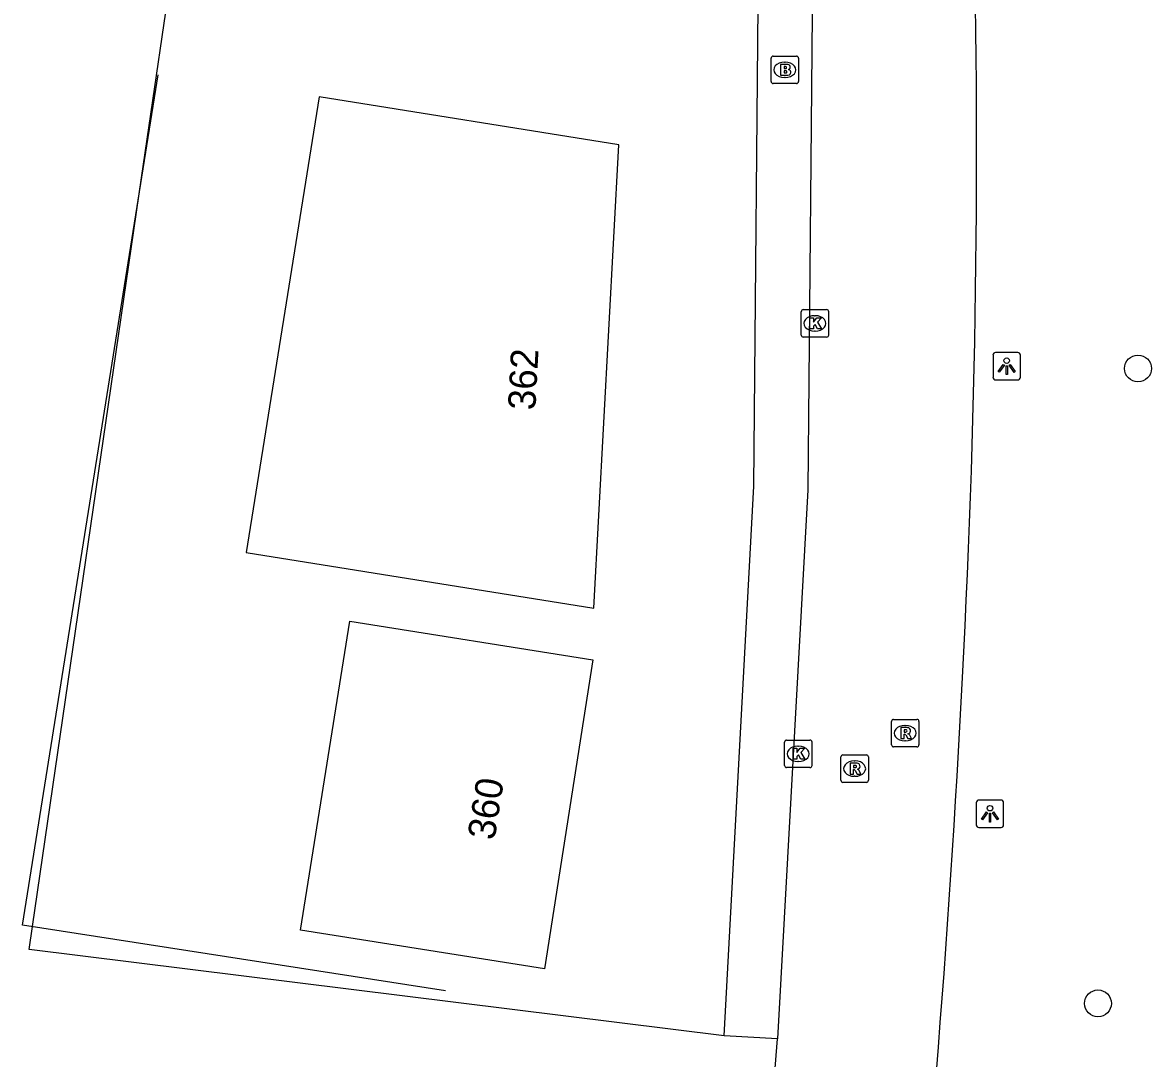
# Model space of a CAD drawing. Extents: x 154324 to 155743, y 382939 to 384183.
# Drawn here: x 155354.48 to 155395.6, y 383333.57 to 383371.29 of the extents above; entities that cross this region are included whole.
import ezdxf

# ---------------------------------------------------------------- set-up
doc = ezdxf.new("R2010")
doc.units = 0
for name, color, linetype in [('IMGEO_Boom', 7, 'Continuous'), ('IMGEO_Brandkraan', 7, 'Continuous'), ('IMGEO_Groenvoorziening', 7, 'Continuous'), ('IMGEO_Hek', 7, 'Continuous'), ('IMGEO_Kolk', 7, 'Continuous'), ('IMGEO_Lichtpunt', 7, 'Continuous'), ('IMGEO_Pand', 7, 'Continuous'), ('IMGEO_Pand_nummerreeks', 7, 'Continuous'), ('IMGEO_Rijbaan_lokaal_open', 7, 'Continuous'), ('IMGEO_Rioolput', 7, 'Continuous'), ('IMGEO_Voetpad_open', 7, 'Continuous')]:
    doc.layers.add(name, color=color, linetype=linetype)

msp = doc.modelspace()

# ---------------------------------------------------------------- linework, layer by layer
at = {"layer": 'IMGEO_Boom'}
for centre in [(155395.106, 383358.693), (155393.648, 383335.575)]:
    msp.add_circle(centre, 0.489, dxfattribs=at)
at = {"layer": 'IMGEO_Brandkraan'}
for p, q in [((155381.816, 383370.068), (155382.668, 383370.068)), ((155381.741, 383369.142), (155381.741, 383369.994)), ((155382.229, 383369.848), (155382.254, 383369.848)), ((155382.742, 383369.994), (155382.742, 383369.142)), ((155382.252, 383369.288), (155382.227, 383369.288)), ((155382.668, 383369.068), (155381.816, 383369.068))]:
    msp.add_line(p, q, dxfattribs=at)
for points in [[(155381.816, 383370.068), (155382.668, 383370.068)], [(155381.741, 383369.142), (155381.741, 383369.994)], [(155382.089, 383369.768), (155382.089, 383369.368), (155382.302, 383369.368)], [(155382.32, 383369.768), (155382.089, 383369.768)], [(155382.268, 383369.687), (155382.214, 383369.687), (155382.214, 383369.611)], [(155382.742, 383369.994), (155382.742, 383369.142)], [(155382.214, 383369.611), (155382.267, 383369.611)], [(155382.276, 383369.535), (155382.214, 383369.535), (155382.214, 383369.454)], [(155382.214, 383369.454), (155382.276, 383369.454)], [(155382.668, 383369.068), (155381.816, 383369.068)]]:
    msp.add_lwpolyline(points, dxfattribs=at)
for centre, radius, start, end in [((155381.818, 383369.992), 0.0765, 91.552, 178.448), ((155381.818, 383369.992), 0.0765, 91.552, 178.448), ((155382.666, 383369.992), 0.0765, 1.552, 88.448), ((155382.666, 383369.992), 0.0765, 1.552, 88.448), ((155382.269, 383369.649), 0.0379, 267.8285, 90.9355), ((155382.324, 383369.623), 0.145, 59.4692, 91.5367), ((155382.349, 383369.67), 0.0922, 285.5137, 58.1501), ((155382.277, 383369.494), 0.0404, 269.8759, 90.5077), ((155382.308, 383369.619), 0.251, 268.6676, 293.5347), ((155382.354, 383369.478), 0.105, 301.3115, 78.989), ((155381.818, 383369.144), 0.0765, 181.552, 268.448), ((155381.818, 383369.144), 0.0765, 181.552, 268.448), ((155382.666, 383369.144), 0.0765, 271.552, 358.448), ((155382.666, 383369.144), 0.0765, 271.552, 358.448)]:
    msp.add_arc(centre, radius, start, end, dxfattribs=at)
for centre, major_axis, ratio, start_param, end_param in [((155382.228, 383369.568), (-0.387, 0.002), 0.722429, 4.712389, 7.853982), ((155382.253, 383369.568), (-0.39, 0.002), 0.717154, 1.570796, 4.712389)]:
    msp.add_ellipse(centre, major_axis=major_axis, ratio=ratio, start_param=start_param, end_param=end_param, dxfattribs=at)
at = {"layer": 'IMGEO_Groenvoorziening'}
msp.add_lwpolyline([(155380.034, 383334.398), (155354.723, 383337.539), (155354.844, 383338.369), (155358.814, 383365.632), (155360.106, 383374.508)], dxfattribs=at)
at = {"layer": 'IMGEO_Hek'}
msp.add_lwpolyline([(155369.884, 383336.037), (155354.478, 383338.426), (155359.411, 383369.381)], dxfattribs=at)
at = {"layer": 'IMGEO_Kolk'}
for p, q in [((155382.838, 383359.91), (155382.838, 383360.762)), ((155382.913, 383360.836), (155383.765, 383360.836)), ((155383.326, 383360.616), (155383.351, 383360.616)), ((155383.839, 383360.762), (155383.839, 383359.91)), ((155383.765, 383359.836), (155382.913, 383359.836)), ((155383.349, 383360.056), (155383.324, 383360.056)), ((155382.231, 383344.237), (155382.231, 383345.089)), ((155382.306, 383345.163), (155383.158, 383345.163)), ((155383.232, 383345.089), (155383.232, 383344.237)), ((155382.719, 383344.943), (155382.744, 383344.943)), ((155383.158, 383344.163), (155382.306, 383344.163)), ((155382.742, 383344.383), (155382.717, 383344.383))]:
    msp.add_line(p, q, dxfattribs=at)
for points in [[(155382.838, 383359.91), (155382.838, 383360.762)], [(155382.913, 383360.836), (155383.765, 383360.836)], [(155383.839, 383360.762), (155383.839, 383359.91)], [(155383.159, 383360.536), (155383.282, 383360.536), (155383.282, 383360.385), (155383.412, 383360.536), (155383.576, 383360.536), (155383.43, 383360.385), (155383.583, 383360.136), (155383.431, 383360.136), (155383.346, 383360.3), (155383.282, 383360.233), (155383.282, 383360.136), (155383.159, 383360.136), (155383.159, 383360.536)], [(155383.765, 383359.836), (155382.913, 383359.836)], [(155382.231, 383344.237), (155382.231, 383345.089)], [(155382.306, 383345.163), (155383.158, 383345.163)], [(155383.232, 383345.089), (155383.232, 383344.237)], [(155382.552, 383344.863), (155382.675, 383344.863), (155382.675, 383344.712), (155382.805, 383344.863), (155382.969, 383344.863), (155382.823, 383344.712), (155382.976, 383344.463), (155382.824, 383344.463), (155382.739, 383344.627), (155382.675, 383344.56), (155382.675, 383344.463), (155382.552, 383344.463), (155382.552, 383344.863)], [(155383.158, 383344.163), (155382.306, 383344.163)]]:
    msp.add_lwpolyline(points, dxfattribs=at)
for centre, start, end in [((155382.915, 383360.76), 91.552, 178.448), ((155382.915, 383360.76), 91.552, 178.448), ((155383.763, 383360.76), 1.552, 88.448), ((155383.763, 383360.76), 1.552, 88.448), ((155382.915, 383359.912), 181.552, 268.448), ((155382.915, 383359.912), 181.552, 268.448), ((155383.763, 383359.912), 271.552, 358.448), ((155383.763, 383359.912), 271.552, 358.448), ((155382.308, 383345.087), 91.552, 178.448), ((155382.308, 383345.087), 91.552, 178.448), ((155383.156, 383345.087), 1.552, 88.448), ((155383.156, 383345.087), 1.552, 88.448), ((155382.308, 383344.239), 181.552, 268.448), ((155382.308, 383344.239), 181.552, 268.448), ((155383.156, 383344.239), 271.552, 358.448), ((155383.156, 383344.239), 271.552, 358.448)]:
    msp.add_arc(centre, 0.0765, start, end, dxfattribs=at)
for centre, major_axis, ratio, start_param, end_param in [((155383.325, 383360.336), (-0.387, 0.002), 0.722429, 4.712389, 7.853982), ((155383.35, 383360.336), (-0.39, 0.002), 0.717154, 1.570796, 4.712389), ((155382.718, 383344.663), (-0.387, 0.002), 0.722429, 4.712389, 7.853982), ((155382.743, 383344.663), (-0.39, 0.002), 0.717154, 1.570796, 4.712389)]:
    msp.add_ellipse(centre, major_axis=major_axis, ratio=ratio, start_param=start_param, end_param=end_param, dxfattribs=at)
at = {"layer": 'IMGEO_Lichtpunt'}
for p, q in [((155389.825, 383359.18), (155389.825, 383358.373)), ((155389.825, 383359.18), (155389.825, 383358.373)), ((155390.727, 383359.275), (155389.919, 383359.275)), ((155390.727, 383359.275), (155389.919, 383359.275)), ((155390.821, 383358.373), (155390.821, 383359.18)), ((155390.821, 383358.373), (155390.821, 383359.18)), ((155389.919, 383358.279), (155390.727, 383358.279)), ((155389.919, 383358.279), (155390.727, 383358.279)), ((155390.118, 383342.978), (155389.31, 383342.978)), ((155390.118, 383342.978), (155389.31, 383342.978)), ((155389.216, 383342.883), (155389.216, 383342.076)), ((155389.216, 383342.883), (155389.216, 383342.076)), ((155390.212, 383342.076), (155390.212, 383342.883)), ((155390.212, 383342.076), (155390.212, 383342.883)), ((155389.31, 383341.982), (155390.118, 383341.982)), ((155389.31, 383341.982), (155390.118, 383341.982))]:
    msp.add_line(p, q, dxfattribs=at)
for points in [[(155390.199, 383358.844), (155390.238, 383358.816), (155390.05, 383358.554), (155390.012, 383358.581), (155390.199, 383358.844)], [(155390.301, 383358.796), (155390.348, 383358.796), (155390.348, 383358.474), (155390.301, 383358.474), (155390.301, 383358.796)], [(155390.411, 383358.816), (155390.449, 383358.843), (155390.636, 383358.581), (155390.597, 383358.553), (155390.411, 383358.816)], [(155389.59, 383342.547), (155389.629, 383342.519), (155389.441, 383342.257), (155389.403, 383342.284), (155389.59, 383342.547)], [(155389.802, 383342.519), (155389.84, 383342.546), (155390.027, 383342.284), (155389.988, 383342.256), (155389.802, 383342.519)], [(155389.692, 383342.499), (155389.739, 383342.499), (155389.739, 383342.177), (155389.692, 383342.177), (155389.692, 383342.499)]]:
    msp.add_lwpolyline(points, dxfattribs=at)
for centre in [(155390.324, 383358.978), (155389.715, 383342.681)]:
    msp.add_circle(centre, 0.0994, dxfattribs=at)
for centre, start, end in [((155389.919, 383359.18), 90, 180), ((155389.919, 383359.18), 90, 180), ((155390.727, 383359.18), 0, 90), ((155390.727, 383359.18), 0, 90), ((155389.919, 383358.373), 180, 270), ((155389.919, 383358.373), 180, 270), ((155390.727, 383358.373), 270, 0), ((155390.727, 383358.373), 270, 360), ((155389.31, 383342.883), 90, 180), ((155389.31, 383342.883), 90, 180), ((155390.118, 383342.883), 0, 90), ((155390.118, 383342.883), 0, 90), ((155389.31, 383342.076), 180, 270), ((155389.31, 383342.076), 180, 270), ((155390.118, 383342.076), 270, 0), ((155390.118, 383342.076), 270, 360)]:
    msp.add_arc(centre, 0.0946, start, end, dxfattribs=at)
at = {"layer": 'IMGEO_Pand'}
for points in [[(155376.195, 383366.839), (155365.283, 383368.59), (155362.62, 383351.999), (155375.291, 383349.97), (155376.195, 383366.839)], [(155366.404, 383349.488), (155375.255, 383348.08), (155373.484, 383336.828), (155364.602, 383338.245), (155366.404, 383349.488)]]:
    msp.add_lwpolyline(points, dxfattribs=at)
at = {"layer": 'IMGEO_Rijbaan_lokaal_open'}
msp.add_lwpolyline([(155383.12, 383377.352), (155383.264, 383374.318), (155383.19, 383366.215), (155383.081, 383354.275), (155381.974, 383334.287)], dxfattribs=at)
for centre, radius, start, end in [((155026.251, 383366.771), 362.977, 356.94684, 1.70249), ((154889.758, 383373.172), 499.618, 353.74726, 357.04758), ((155071.527, 383356.622), 311.25, 352.27674, 355.8849)]:
    msp.add_arc(centre, radius, start, end, dxfattribs=at)
at = {"layer": 'IMGEO_Rioolput'}
for p, q in [((155386.127, 383344.991), (155386.127, 383345.843)), ((155386.202, 383345.917), (155387.054, 383345.917)), ((155387.128, 383345.843), (155387.128, 383344.991)), ((155386.615, 383345.697), (155386.64, 383345.697)), ((155386.638, 383345.137), (155386.613, 383345.137)), ((155384.36, 383344.624), (155385.212, 383344.624)), ((155387.054, 383344.917), (155386.202, 383344.917)), ((155384.285, 383343.698), (155384.285, 383344.55)), ((155384.773, 383344.404), (155384.798, 383344.404)), ((155385.286, 383344.55), (155385.286, 383343.698)), ((155384.796, 383343.844), (155384.771, 383343.844)), ((155385.212, 383343.624), (155384.36, 383343.624))]:
    msp.add_line(p, q, dxfattribs=at)
for points in [[(155386.127, 383344.991), (155386.127, 383345.843)], [(155386.202, 383345.917), (155387.054, 383345.917)], [(155387.128, 383345.843), (155387.128, 383344.991)], [(155386.716, 383345.615), (155386.464, 383345.617), (155386.464, 383345.217)], [(155386.642, 383345.536), (155386.588, 383345.536), (155386.588, 383345.455)], [(155386.588, 383345.455), (155386.64, 383345.455)], [(155386.464, 383345.217), (155386.588, 383345.217), (155386.588, 383345.379), (155386.599, 383345.379)], [(155386.646, 383345.35), (155386.717, 383345.217), (155386.857, 383345.217), (155386.792, 383345.343)], [(155384.36, 383344.624), (155385.212, 383344.624)], [(155387.054, 383344.917), (155386.202, 383344.917)], [(155384.285, 383343.698), (155384.285, 383344.55)], [(155384.874, 383344.322), (155384.622, 383344.324), (155384.622, 383343.924)], [(155384.8, 383344.243), (155384.746, 383344.243), (155384.746, 383344.162)], [(155384.746, 383344.162), (155384.798, 383344.162)], [(155385.286, 383344.55), (155385.286, 383343.698)], [(155384.622, 383343.924), (155384.746, 383343.924), (155384.746, 383344.086), (155384.757, 383344.086)], [(155384.804, 383344.057), (155384.875, 383343.924), (155385.015, 383343.924), (155384.95, 383344.05)], [(155385.212, 383343.624), (155384.36, 383343.624)]]:
    msp.add_lwpolyline(points, dxfattribs=at)
for centre, radius, start, end in [((155386.204, 383345.841), 0.0765, 91.552, 178.448), ((155386.204, 383345.841), 0.0765, 91.552, 178.448), ((155387.052, 383345.841), 0.0765, 1.552, 88.448), ((155387.052, 383345.841), 0.0765, 1.552, 88.448), ((155386.624, 383345.644), 0.19, 274.7715, 282.9687), ((155386.648, 383345.44), 0.0964, 77.0061, 93.1865), ((155386.662, 383345.497), 0.0378, 276.6634, 79.6772), ((155386.715, 383345.505), 0.109, 350.3612, 89.416), ((155386.713, 383345.505), 0.112, 277.5842, 350.9817), ((155386.697, 383345.29), 0.108, 29.5134, 73.7905), ((155386.204, 383344.993), 0.0765, 181.552, 268.448), ((155386.204, 383344.993), 0.0765, 181.552, 268.448), ((155386.598, 383345.326), 0.0533, 26.0293, 88.6989), ((155387.052, 383344.993), 0.0765, 271.552, 358.448), ((155387.052, 383344.993), 0.0765, 271.552, 358.448), ((155384.362, 383344.548), 0.0765, 91.552, 178.448), ((155384.362, 383344.548), 0.0765, 91.552, 178.448), ((155385.21, 383344.548), 0.0765, 1.552, 88.448), ((155385.21, 383344.548), 0.0765, 1.552, 88.448), ((155384.782, 383344.351), 0.19, 274.7715, 282.9687), ((155384.806, 383344.147), 0.0964, 77.0061, 93.1865), ((155384.82, 383344.204), 0.0378, 276.6634, 79.6772), ((155384.873, 383344.212), 0.109, 350.3612, 89.416), ((155384.871, 383344.212), 0.112, 277.5842, 350.9817), ((155384.756, 383344.033), 0.0533, 26.0293, 88.6989), ((155384.855, 383343.997), 0.108, 29.5134, 73.7905), ((155384.362, 383343.7), 0.0765, 181.552, 268.448), ((155384.362, 383343.7), 0.0765, 181.552, 268.448), ((155385.21, 383343.7), 0.0765, 271.552, 358.448), ((155385.21, 383343.7), 0.0765, 271.552, 358.448)]:
    msp.add_arc(centre, radius, start, end, dxfattribs=at)
for centre, major_axis, ratio, start_param, end_param in [((155386.614, 383345.417), (-0.387, 0.002), 0.722429, 4.712389, 7.853982), ((155386.639, 383345.417), (-0.39, 0.002), 0.717154, 1.570796, 4.712389), ((155384.772, 383344.124), (-0.387, 0.002), 0.722429, 4.712389, 7.853982), ((155384.797, 383344.124), (-0.39, 0.002), 0.717154, 1.570796, 4.712389)]:
    msp.add_ellipse(centre, major_axis=major_axis, ratio=ratio, start_param=start_param, end_param=end_param, dxfattribs=at)
at = {"layer": 'IMGEO_Voetpad_open'}
for points in [[(155380.034, 383334.398), (155381.119, 383354.403), (155381.295, 383374.612), (155381.184, 383376.925)], [(155381.974, 383334.287), (155380.034, 383334.398)]]:
    msp.add_lwpolyline(points, dxfattribs=at)

# ---------------------------------------------------------------- texts
at = {"layer": 'IMGEO_Pand_nummerreeks'}
for s, rotation, p in [('362', 86.9313, (155373.153, 383357.159)), ('360', 81.0531, (155371.667, 383341.491))]:
    msp.add_text(s, height=1, rotation=rotation, dxfattribs=at).set_placement(p)

doc.saveas('drawing.dxf')
